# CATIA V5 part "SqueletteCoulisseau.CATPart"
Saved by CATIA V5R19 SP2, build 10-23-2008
Part number: SqueletteCoulisseau
Publications: "BodyCoulisseau"
Bounding box of the stored display mesh (mm): x -10 to 10, y -10 to 32, z 0 to 175
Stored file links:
  D:\France\IFMA\IAO\Projet\SqueletteCoulisseau.CATPart
  D:\France\IFMA\IAO\Projet\pruangdaja_CAO.CATProduct
  D:\France\IFMA\IAO\Projet\SqueletteAB.CATPart
  D:\France\IFMA\IAO\Projet\SqueletteBCD.CATPart
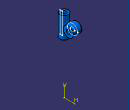
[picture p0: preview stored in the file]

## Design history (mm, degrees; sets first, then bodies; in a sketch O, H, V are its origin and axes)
Parameters
  LENGTH = 10 mm
  D_Coulisseau = 12 mm
External parameters (linked from other documents)
  External.HauteurB = 150 mm
  External.LongueurB = 20 mm
  External.Largeur = 10 mm
  External.LongueurAB = 180 mm
  External.RayonTrouBCD = 5 mm
Set1
  Point1: linked copy from another document
  Point2: linked copy from another document
  Plane1: linked copy from another document
  Point3 "Point.1": linked copy from another document
Set2
  Sketch1, origin (0, 0, 0), H (0, 1, 0), V (0, 0, 1)
    circle A1 centre (20, 150) radius 12
    point P1 (20, 150)
    circle A2 centre (20, 150) radius 5
    reference projected point E1 (20, 150) from Point1
    radius A1 = 12 {= External.Largeur +2mm}
    radius A2 = 5 {= External.RayonTrouBCD}
    coincidence: P1 E1
  Sketch2 on Plane1, origin (0, 0, 0), H (0, 1, 0), V (0, 0, 1)
    line L1 (-5, 125) -> (-10, 125)
    line L2 (-10, 125) -> (-10, 175)
    line L3 (-10, 175) -> (-5, 175)
    line L4 (-5, 175) -> (-5, 125)
    reference projected point E1 (20, 150) from Point1
    reference projected point E2 (20, 150) from Point1
    reference projected point E3 (0, 90) from Point2
    reference projected point E4 (0, 90) from Point2
    distance E1 L1 = 25
    distance E2 L3 = 25
    distance L4 E3 = 5 {= External.Largeur /2}
    distance E4 L2 = 10 {= D_Coulisseau -2mm}
    horizontal: L1 H, L3 H
    vertical: L2 V, L4 V
Body1 (main body)
  Shaft1: profile Sketch2, axis Z axis, angle 360
  Pad1: profile Sketch1, direction (1, 0, 0), length 10 {= External.Largeur}, mirrored extent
